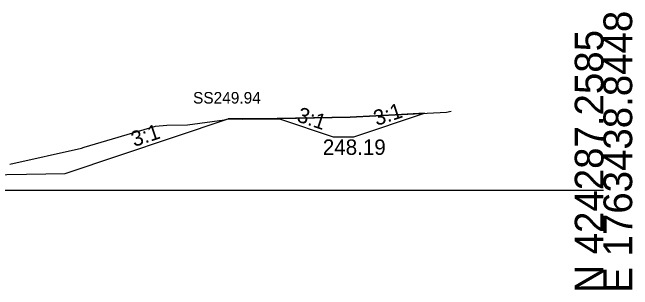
# Model space of a CAD drawing. Extents: x -26 to 3203, y -11010 to 4024.
# Drawn here: x 2142.3 to 2202.8, y -2509.7 to -2482.7 of the extents above; entities that cross this region are included whole.
import ezdxf

# ---------------------------------------------------------------- set-up
doc = ezdxf.new("R2010")
doc.units = 0
for name, color, linetype in [('Exist Cross Section Cell', 7, 'Continuous'), ('Exist XS Ground Line', 7, 'Continuous'), ('Prop CMT Ditch DDE', 7, 'Continuous'), ('Prop CMT Slope Grass', 7, 'Continuous'), ('Prop XS Ditch Standard Text', 7, 'Continuous'), ('Prop XS Side Slope Text', 7, 'Continuous'), ('Prop XS SS Elevation Text', 7, 'Continuous'), ('Scratch_Level_0', 7, 'Continuous')]:
    doc.layers.add(name, color=color, linetype=linetype)

msp = doc.modelspace()

# ---------------------------------------------------------------- linework, layer by layer
at = {"layer": 'Exist Cross Section Cell'}
msp.add_line((2100, -2500), (2200, -2500), dxfattribs=at)
at = {"layer": 'Exist XS Ground Line'}
msp.add_lwpolyline([(2142.113, -2497.48), (2149.09, -2495.895), (2149.347, -2495.824), (2156.303, -2493.755), (2157.408, -2493.663), (2159.427, -2493.629), (2163.036, -2493.146), (2163.398, -2493.063), (2164.818, -2493.096), (2175.302, -2492.878), (2180.288, -2492.64), (2184.684, -2492.391), (2185.128, -2492.315)], dxfattribs=at)
msp.add_lwpolyline([(2142.113, -2497.48), (2149.09, -2495.895), (2149.347, -2495.824), (2156.303, -2493.755), (2157.408, -2493.663), (2159.427, -2493.629), (2163.036, -2493.146), (2163.398, -2493.063), (2164.818, -2493.096), (2175.302, -2492.878), (2180.288, -2492.64), (2184.684, -2492.391), (2185.128, -2492.315)], dxfattribs=at)
msp.add_lwpolyline([(2142.113, -2497.48), (2149.09, -2495.895), (2149.347, -2495.824), (2156.303, -2493.755), (2157.408, -2493.663), (2159.427, -2493.629), (2163.036, -2493.146), (2163.398, -2493.063), (2164.818, -2493.096), (2175.302, -2492.878), (2180.288, -2492.64), (2184.684, -2492.391), (2185.128, -2492.315)], dxfattribs=at)
msp.add_lwpolyline([(2142.113, -2497.48), (2149.09, -2495.895), (2149.347, -2495.824), (2156.303, -2493.755), (2157.408, -2493.663), (2159.427, -2493.629), (2163.036, -2493.146), (2163.398, -2493.063), (2164.818, -2493.096), (2175.302, -2492.878), (2180.288, -2492.64), (2184.684, -2492.391), (2185.128, -2492.315)], dxfattribs=at)
msp.add_lwpolyline([(2142.113, -2497.48), (2149.09, -2495.895), (2149.347, -2495.824), (2156.303, -2493.755), (2157.408, -2493.663), (2159.427, -2493.629), (2163.036, -2493.146), (2163.398, -2493.063), (2164.818, -2493.096), (2175.302, -2492.878), (2180.288, -2492.64), (2184.684, -2492.391), (2185.128, -2492.315)], dxfattribs=at)
at = {"layer": 'Prop CMT Ditch DDE'}
msp.add_lwpolyline([(2163.404, -2493.063), (2168.404, -2493.063), (2173.647, -2494.811), (2175.647, -2494.811), (2182.542, -2492.512)], dxfattribs=at)
at = {"layer": 'Prop CMT Slope Grass'}
msp.add_lwpolyline([(2138.001, -2498.554), (2147.501, -2498.364), (2163.404, -2493.063)], dxfattribs=at)
at = {"layer": 'Scratch_Level_0'}
for p, q in [((2182.542, -2492.512), (2180.288, -2492.64)), ((2163.404, -2493.063), (2164.818, -2493.096)), ((2166.383, -2493.063), (2163.404, -2493.063)), ((2164.818, -2493.096), (2166.383, -2493.063)), ((2166.383, -2493.063), (2168.404, -2493.063))]:
    msp.add_line(p, q, dxfattribs=at)
for points in [[(2180.288, -2492.64), (2175.302, -2492.878), (2166.383, -2493.063)], [(2168.404, -2493.063), (2173.647, -2494.811), (2175.647, -2494.811), (2182.542, -2492.512)]]:
    msp.add_lwpolyline(points, dxfattribs=at)

# ---------------------------------------------------------------- texts
at = {"layer": 'Exist Cross Section Cell'}
for s, p in [('E 1763438.8448', (2202.8, -2510)), ('N 424287.2585', (2200, -2510))]:
    msp.add_text(s, height=2.8, rotation=90, dxfattribs=at).set_placement(p)
at = {"layer": 'Prop XS Ditch Standard Text'}
msp.add_text('248.19', height=1.5, dxfattribs=at).set_placement((2172.627, -2496.561))
at = {"layer": 'Prop XS Side Slope Text'}
for rotation, p in [(18.43493, (2177.872, -2493.753)), (341.56507, (2169.992, -2493.276)), (18.43493, (2154.23, -2495.805))]:
    msp.add_text('3:1', height=1.5, rotation=rotation, dxfattribs=at).set_placement(p)
at = {"layer": 'Prop XS SS Elevation Text'}
msp.add_text('SS249.94', height=1.125, dxfattribs=at).set_placement((2159.968, -2491.561))
msp.add_text('SS249.94', height=1.125, dxfattribs=at).set_placement((2159.968, -2491.561))
at = {"layer": 'Scratch_Level_0'}
for s, p in [('RT_DD_Boundary Out', (2182.373, -2492.522)), ('Exterior Boundary', (2182.384, -2492.522)), ('RT_Slope_Cut', (2163.3, -2493.073)), ('RT_DD_Boundary In', (2168.251, -2493.073)), ('RT_DD_Base In', (2173.534, -2494.821)), ('RT_DD_Base Out', (2175.517, -2494.821)), ('RT_CSLP_Pnt', (2147.402, -2498.374))]:
    msp.add_text(s, height=0.02, dxfattribs=at).set_placement(p)

doc.saveas('drawing.dxf')
